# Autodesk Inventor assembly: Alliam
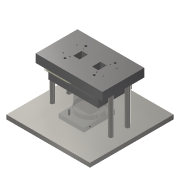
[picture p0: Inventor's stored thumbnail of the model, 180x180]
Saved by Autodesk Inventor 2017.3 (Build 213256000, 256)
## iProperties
Part Number: Alliam
Material: 一般
Document SubType Name: Assembly
Designer: kyushu-hep
Author: kyushu-hep
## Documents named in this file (8)
- C:\Users\kyushu-hep\Desktop\dkobayas\FlexAssembly3\Alliam.iam
- C:\Users\kyushu-hep\Desktop\dkobayas\FlexAssembly3\FlexBase.ipt
- C:\Users\kyushu-hep\Desktop\dkobayas\FlexAssembly3\ModuleBase.ipt
- C:\Users\kyushu-hep\Desktop\dkobayas\FlexAssembly3\Module.ipt
- C:\Users\kyushu-hep\Desktop\dkobayas\FlexAssembly3\FPC2.ipt
- C:\Users\kyushu-hep\Desktop\dkobayas\FlexAssembly3\base1.ipt
- C:\Users\kyushu-hep\Desktop\dkobayas\FlexAssembly3\ClearBoard.ipt
- C:\Users\kyushu-hep\Desktop\dkobayas\FlexAssembly3\Stages.ipt
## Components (7 placed, 7 different names)
1. FlexBase:1 — メイト:18, メイト:19, メイト:20, メイト:21, メイト:22, メイト:32, メイト:33
2. base1:1 — メイト:13, メイト:14, メイト:26, メイト:27, メイト:28, メイト:32, メイト:33
3. FPC2:1 — メイト:21, メイト:22, メイト:23
4. ModuleBase:1 — メイト:15, メイト:16, メイト:17, メイト:31
5. Module:1 — メイト:15, メイト:16, メイト:17
6. ClearBoard:1 — メイト:18, メイト:19, メイト:20, メイト:23
7. Stages:1 — メイト:26, メイト:27, メイト:28, メイト:31
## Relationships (17: Mate 17)
- メイト:13 [Mate]: base1:1
- メイト:14 [Mate]: base1:1
- メイト:15 [Mate]: ModuleBase:1 ↔ Module:1
- メイト:16 [Mate]: ModuleBase:1 ↔ Module:1
- メイト:17 [Mate]: ModuleBase:1 ↔ Module:1
- メイト:18 [Mate]: FlexBase:1 ↔ ClearBoard:1
- メイト:19 [Mate]: FlexBase:1 ↔ ClearBoard:1
- メイト:20 [Mate]: FlexBase:1 ↔ ClearBoard:1
- メイト:21 [Mate]: FlexBase:1 ↔ FPC2:1
- メイト:22 [Mate]: FlexBase:1 ↔ FPC2:1
- メイト:23 [Mate]: FPC2:1 ↔ ClearBoard:1
- メイト:26 [Mate]: base1:1 ↔ Stages:1
- メイト:27 [Mate]: base1:1 ↔ Stages:1
- メイト:28 [Mate]: base1:1 ↔ Stages:1
- メイト:31 [Mate]: ModuleBase:1 ↔ Stages:1
- メイト:32 [Mate]: FlexBase:1 ↔ base1:1
- メイト:33 [Mate]: FlexBase:1 ↔ base1:1
